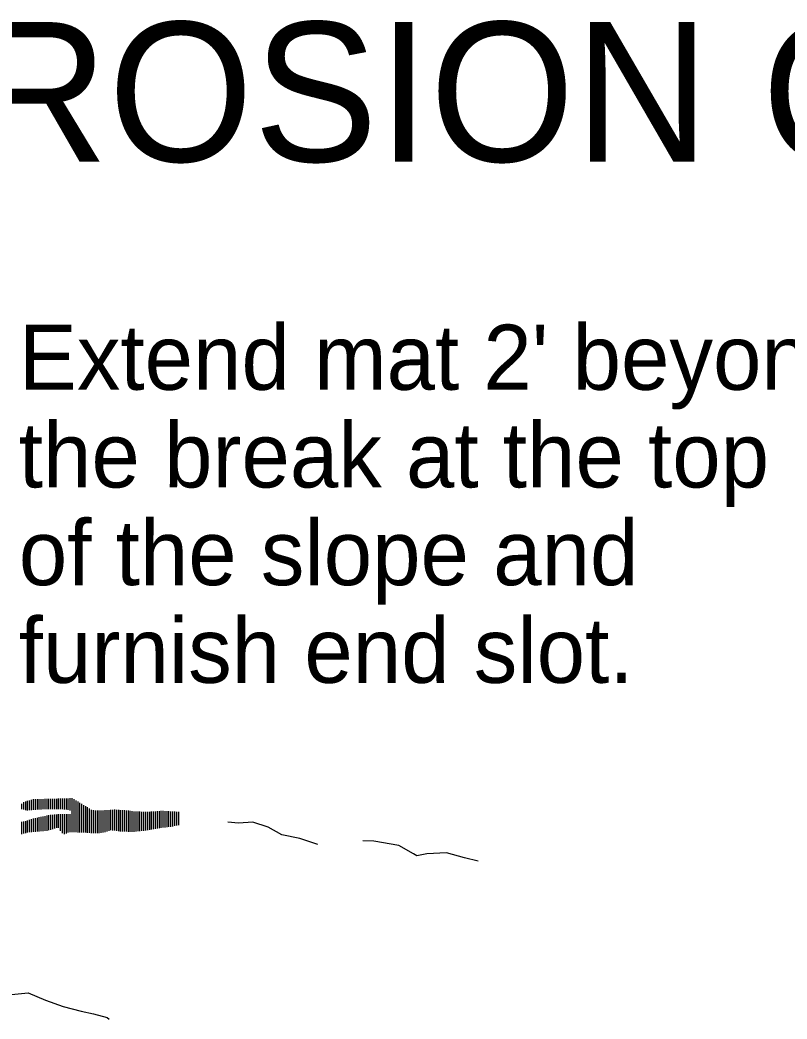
# Model space of a CAD drawing. Extents: x 1083.1 to 1117.1, y 719.4 to 741.4.
# Drawn here: x 1096.807 to 1098.457, y 723.5 to 725.648 of the extents above; entities that cross this region are included whole.
import ezdxf

# ---------------------------------------------------------------- set-up
doc = ezdxf.new("R2010")
doc.units = 0
doc.layers.add('ST_Details', color=7, linetype='Continuous')
doc.layers.add('ST_Text', color=7, linetype='Continuous')

msp = doc.modelspace()

# ---------------------------------------------------------------- linework, layer by layer
at = {"layer": 'ST_Details'}
for p, q in [((1096.8363, 723.9496), (1096.8363, 723.9723)), ((1096.8405, 723.95), (1096.8405, 723.9724)), ((1096.8447, 723.9504), (1096.8447, 723.9726)), ((1096.8488, 723.9506), (1096.8488, 723.9728)), ((1096.853, 723.9507), (1096.853, 723.9728)), ((1096.8572, 723.9509), (1096.8572, 723.9729)), ((1096.8613, 723.951), (1096.8613, 723.9731)), ((1096.8655, 723.9512), (1096.8655, 723.9732)), ((1096.8697, 723.9513), (1096.8697, 723.9733)), ((1096.8738, 723.9515), (1096.8738, 723.9734)), ((1096.878, 723.9514), (1096.878, 723.9735)), ((1096.8822, 723.9514), (1096.8822, 723.9736)), ((1096.8863, 723.9512), (1096.8863, 723.9737)), ((1096.8905, 723.9511), (1096.8905, 723.9738)), ((1096.8947, 723.9511), (1096.8947, 723.9739)), ((1096.8988, 723.9509), (1096.8988, 723.9741)), ((1096.903, 723.9507), (1096.903, 723.9742)), ((1096.9072, 723.9507), (1096.9072, 723.9743)), ((1096.9113, 723.9495), (1096.9113, 723.9744)), ((1096.9155, 723.948), (1096.9155, 723.9746)), ((1096.9197, 723.9017), (1096.9197, 723.9747)), ((1096.9238, 723.9016), (1096.9238, 723.9725)), ((1096.8113, 723.9511), (1096.8113, 723.9624)), ((1096.8155, 723.9501), (1096.8155, 723.9664)), ((1096.8197, 723.949), (1096.8197, 723.9676)), ((1096.8238, 723.9484), (1096.8238, 723.9688)), ((1096.828, 723.9489), (1096.828, 723.9699)), ((1096.8322, 723.9493), (1096.8322, 723.9711)), ((1096.928, 723.9015), (1096.928, 723.97)), ((1096.9322, 723.9013), (1096.9322, 723.9676)), ((1096.9363, 723.9012), (1096.9363, 723.9651)), ((1096.9405, 723.9011), (1096.9405, 723.9626)), ((1096.9447, 723.9009), (1096.9447, 723.9601)), ((1096.9488, 723.9007), (1096.9488, 723.9576)), ((1096.9529, 723.9004), (1096.9529, 723.9551)), ((1096.9571, 723.9002), (1096.9571, 723.9526)), ((1096.8322, 723.902), (1096.8322, 723.9295)), ((1096.8363, 723.9023), (1096.8363, 723.9308)), ((1096.8405, 723.9027), (1096.8405, 723.9319)), ((1096.8447, 723.903), (1096.8447, 723.9327)), ((1096.8488, 723.9033), (1096.8488, 723.9338)), ((1096.853, 723.9037), (1096.853, 723.9346)), ((1096.8572, 723.904), (1096.8572, 723.9354)), ((1096.8613, 723.9043), (1096.8613, 723.9363)), ((1096.8655, 723.9047), (1096.8655, 723.9372)), ((1096.8697, 723.9058), (1096.8697, 723.9381)), ((1096.8738, 723.907), (1096.8738, 723.9388)), ((1096.878, 723.9082), (1096.878, 723.9391)), ((1096.8822, 723.9095), (1096.8822, 723.9394)), ((1096.8863, 723.9107), (1096.8863, 723.9398)), ((1096.8905, 723.9108), (1096.8905, 723.9401)), ((1096.8947, 723.9049), (1096.8947, 723.9404)), ((1096.8988, 723.8997), (1096.8988, 723.9407)), ((1096.903, 723.8972), (1096.903, 723.9407)), ((1096.9072, 723.8988), (1096.9072, 723.9407)), ((1096.9113, 723.9007), (1096.9113, 723.9407)), ((1096.9155, 723.9018), (1096.9155, 723.9407)), ((1096.9613, 723.8998), (1096.9613, 723.9499)), ((1096.9654, 723.8997), (1096.9654, 723.9488)), ((1096.9696, 723.8993), (1096.9696, 723.9485)), ((1096.9738, 723.8992), (1096.9738, 723.9483)), ((1096.9779, 723.8998), (1096.9779, 723.9481)), ((1096.9821, 723.9005), (1096.9821, 723.9481)), ((1096.9863, 723.9013), (1096.9863, 723.9484)), ((1096.9904, 723.902), (1096.9904, 723.9488)), ((1096.9946, 723.9032), (1096.9946, 723.949)), ((1096.9988, 723.9048), (1096.9988, 723.9493)), ((1097.0029, 723.9062), (1097.0029, 723.9496)), ((1097.0071, 723.9056), (1097.0071, 723.9498)), ((1097.0113, 723.905), (1097.0113, 723.9501)), ((1097.0154, 723.9043), (1097.0154, 723.9497)), ((1097.0196, 723.9038), (1097.0196, 723.9496)), ((1097.0238, 723.9033), (1097.0238, 723.9493)), ((1097.0279, 723.9032), (1097.0279, 723.9491)), ((1097.0321, 723.903), (1097.0321, 723.9488)), ((1097.0363, 723.9028), (1097.0363, 723.9485)), ((1097.0404, 723.9027), (1097.0404, 723.9483)), ((1097.0446, 723.9027), (1097.0446, 723.9477)), ((1097.0488, 723.9025), (1097.0488, 723.9469)), ((1097.0529, 723.9027), (1097.0529, 723.9462)), ((1097.0571, 723.9031), (1097.0571, 723.9461)), ((1097.0613, 723.9035), (1097.0613, 723.946)), ((1097.0654, 723.904), (1097.0654, 723.9459)), ((1097.0696, 723.9043), (1097.0696, 723.9457)), ((1097.0738, 723.9048), (1097.0738, 723.9457)), ((1097.0779, 723.9053), (1097.0779, 723.9456)), ((1097.0821, 723.9058), (1097.0821, 723.9454)), ((1097.0863, 723.9065), (1097.0863, 723.9456)), ((1097.0904, 723.9072), (1097.0904, 723.9459)), ((1097.0946, 723.908), (1097.0946, 723.9462)), ((1097.0988, 723.9087), (1097.0988, 723.9464)), ((1097.1029, 723.9093), (1097.1029, 723.9467)), ((1097.1071, 723.9101), (1097.1071, 723.9471)), ((1097.1113, 723.9108), (1097.1113, 723.9473)), ((1097.1154, 723.9115), (1097.1154, 723.9474)), ((1097.1196, 723.912), (1097.1196, 723.9472)), ((1097.1238, 723.9125), (1097.1238, 723.9469)), ((1097.1278, 723.913), (1097.1278, 723.9467)), ((1097.132, 723.9135), (1097.132, 723.9464)), ((1097.1362, 723.9141), (1097.1362, 723.9462)), ((1097.1403, 723.915), (1097.1403, 723.9459)), ((1097.1445, 723.9158), (1097.1445, 723.9457)), ((1097.1487, 723.9167), (1097.1487, 723.9456)), ((1096.8113, 723.8977), (1096.8113, 723.9241)), ((1096.8155, 723.8987), (1096.8155, 723.9243)), ((1096.8197, 723.8997), (1096.8197, 723.9252)), ((1096.8238, 723.9007), (1096.8238, 723.9267)), ((1096.828, 723.9016), (1096.828, 723.928))]:
    msp.add_line(p, q, dxfattribs=at)
for points in [[(1097.4477, 723.875), (1097.4089, 723.8878), (1097.3702, 723.8957), (1097.3411, 723.9125), (1097.3084, 723.9234), (1097.277, 723.9213), (1097.254, 723.9232)], [(1097.7924, 723.8395), (1097.7634, 723.8463), (1097.7246, 723.8572), (1097.6823, 723.855), (1097.6606, 723.8509), (1097.6533, 723.8548), (1097.6218, 723.8727), (1097.5685, 723.8825), (1097.5443, 723.8834)], [(1096.7283, 723.5638), (1096.7453, 723.5569), (1096.7755, 723.551), (1096.796, 723.5532), (1096.825, 723.5562), (1096.8626, 723.5404), (1096.9002, 723.5266), (1096.9388, 723.5168), (1096.9654, 723.5108), (1096.9945, 723.503), (1096.9994, 723.5)]]:
    msp.add_lwpolyline(points, dxfattribs=at)

# ---------------------------------------------------------------- texts
at = {"layer": 'ST_Text'}
for s, height, p in [('EXCELSIOR EROSION CONTROL MAT INSTALLATION', 0.3, (1094.0321, 725.3433)), ("Extend mat 2' beyond", 0.14, (1096.8049, 724.8527)), ('the break at the top', 0.14, (1096.8049, 724.6427)), ('of the slope and', 0.14, (1096.8049, 724.4327)), ('furnish end slot.', 0.14, (1096.8049, 724.2227))]:
    msp.add_text(s, height=height, dxfattribs=at).set_placement(p)

doc.saveas('drawing.dxf')
